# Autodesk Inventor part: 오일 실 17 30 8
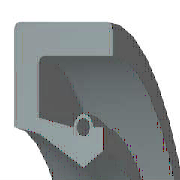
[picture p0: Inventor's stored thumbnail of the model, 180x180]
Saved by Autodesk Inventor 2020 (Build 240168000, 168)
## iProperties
Created: 2012-02
Part Number: 오일 실 17 30 8
Material: 고무
Description: 오일-실
Document SubType Name: Modeling
Standard: KS B 2804
Designer: mduedu
Standards Organization: KS
Language: ko-KR
Size Designation: S - 17 30 8
Categories: <MemberInstance><Categories><Category DisplayName="샤프트 부품" InternalName="7f7aeb1f-a693-4053-b835-cee3144e0d98" Mnemonic="SHFT"><Category DisplayName="실링" Intern
Density: 0.93 g/cm^3
Appearance: 고무 - 검은색 - 버전 1.1
IsCustomPart: 1
Author: mduedu
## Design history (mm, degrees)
revolve "본체" stored, may be unused: angle "d17" = 90 deg
revolve "스프링1" stored, may be unused: angle "d18" = 90 deg
body "Solid1"
sketch "스케치1"
  geometry: L1 (0, 15)-(8, 15); L2 (8, 15)-(8, 13.75); L3 (8, 13.75)-(1.75, 13.75); L4 (0, 15)-(0, 10.6); L5 (0, 10.6)-(1.75, 10.25); L6 (1.75, 10.25)-(4.9, 8.5); L7 (4.9, 8.5)-(0, 8.5); L8 (6.3, 9.375)-(6.3, 10.6); L9 (0, 0)-(9.586, 0) reference; L10 (4.9, 8.5)-(6.3, 9.375); L11 (0, 18)-(0, -3) reference; L12 (-1.917, 0)-(11.503, 0) reference; L13 (4.2, 10.6)-(1.75, 11.09); L14 (1.75, 11.09)-(1.75, 13.75); L15 (6.3, 10.6)-(5.6, 10.6); C1 r 0.455 at (4.9, 10.6); A1 r 0.7 centre (4.9, 10.6) between (5.6, 10.6) and (4.2, 10.6)
  constraints: 26 end point, 5 horizontal alignment, 4 perpendicular, 2 centre point, 2 collinear, 2 horizontal, 2 parallel, 2 point on circle, 2 point on line, 2 vertical alignment, 1 coincident
  dimensions: "d0" = 30 diameter of L1 L9 (= SD2); "d1" = 18.75 diameter of L8.start L9 (= ABDM); "d2" = 1.25 distance of L1.end L2.end (computed from SD); "d3" = 0.91 diameter of C1 (= SPDI); "d4" = 1.4 diameter of A1 (= SPDA); "d5" = 17 diameter of L6.end L9 (= NND); "d6" = 20.5 diameter of L5.end L9 (= TKDM); "d7" = 21.2 diameter of L4.end L9 (= HLDM); "d8" = 4.9 distance from line of C1.centre L4 (= SPDST); "d9" = 6.3 distance between parallel lines of L8 L4 (= SDI); "d10" = 8 distance between parallel lines of L2 L4 (= SWDT); "d12" = 1.75 distance between parallel lines of L14 L4 (= SD)
fillet "모깎기1" dims "d11" = 0.3 (= RR)
other parameters: "SD2" = 30 [user parameter; used in 1 equation term], "SWDT" = 8 [user parameter; used in 1 equation term], "RR" = 0.3 [user parameter; used in 1 equation term], "SD" = 1.75 [user parameter; used in 2 equation terms], "NND" = 17 [user parameter; used in 1 equation term], "SPDA" = 1.4 [user parameter; used in 1 equation term], "SPDI" = 0.91 [user parameter; used in 1 equation term], "TKDM" = 20.5 [user parameter; used in 1 equation term], "HLDM" = 21.2 [user parameter; used in 1 equation term], "ABDM" = 18.75 [user parameter; used in 1 equation term], "SDI" = 6.3 [user parameter; used in 1 equation term], "SPDST" = 4.9 [user parameter; used in 1 equation term], "d13" = 0, "d14" = 0, "d15" = 0, "LAB" = 0.35 [user parameter]
